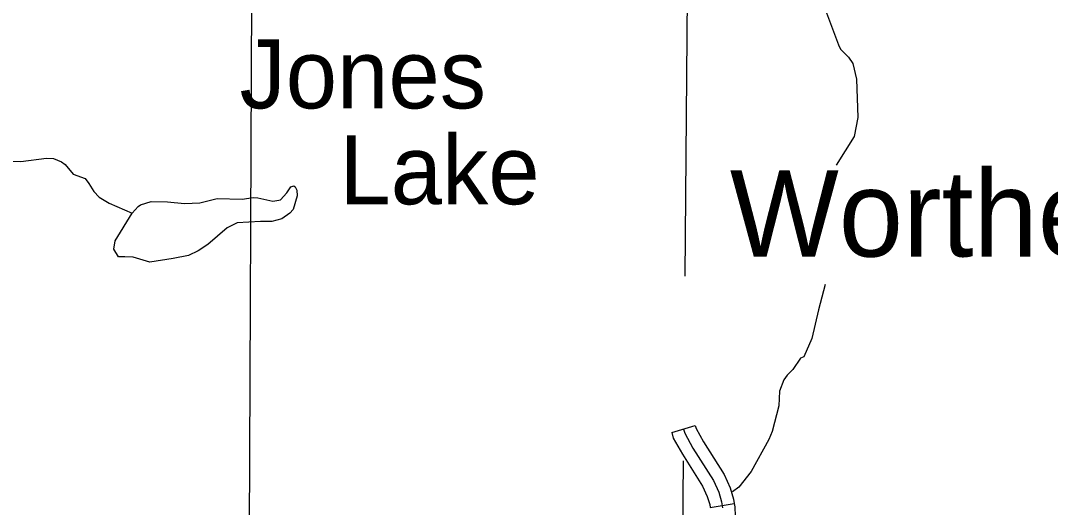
# Model space of a CAD drawing. Extents: x 1374139 to 1377472, y 1168351 to 1170484.
# Drawn here: x 1375895 to 1376021, y 1168985.7 to 1169045.3 of the extents above; entities that cross this region are included whole.
import ezdxf

# ---------------------------------------------------------------- set-up
doc = ezdxf.new("R2010")
doc.units = 0
doc.layers.add('Default', color=7, linetype='Continuous')

msp = doc.modelspace()

# ---------------------------------------------------------------- linework, layer by layer
at = {"layer": 'Default'}
for p, q in [((1375922.99, 1168982), (1375923.67, 1169140.31)), ((1375974.65, 1168994.84), (1375977.52, 1168995.7)), ((1375979.35, 1168985.68), (1375982.31, 1168986.16))]:
    msp.add_line(p, q, dxfattribs=at)
for points in [[(1375976.63, 1169058.15), (1375976.25, 1169014)], [(1375993.35, 1169046.86), (1375995.05, 1169042.32), (1375995.3, 1169041.79), (1375996.27, 1169040.79), (1375996.8, 1169040.04), (1375997.25, 1169038.1), (1375997.41, 1169033.41), (1375996.97, 1169031.09), (1375994.79, 1169027.59)], [(1375891.07, 1169028.08), (1375895.02, 1169028.02), (1375898.17, 1169028.44), (1375899.05, 1169028.38), (1375900, 1169028), (1375900.45, 1169027.67), (1375901.43, 1169026.49), (1375902.89, 1169025.96), (1375903.36, 1169025.35), (1375903.95, 1169024.34), (1375904.61, 1169023.66), (1375905.86, 1169022.91), (1375908.67, 1169021.71), (1375909.37, 1169022.51), (1375909.69, 1169022.74), (1375910.98, 1169023.13), (1375912.96, 1169023.08), (1375915.05, 1169022.87), (1375916.94, 1169022.98), (1375919.05, 1169023.51), (1375922.13, 1169023.43), (1375923.45, 1169023.64), (1375924.01, 1169023.59), (1375925.86, 1169023.18), (1375926.58, 1169023.28), (1375926.8, 1169023.34), (1375927.57, 1169024.18), (1375928.08, 1169024.92), (1375928.41, 1169025.03), (1375928.6, 1169024.93), (1375928.81, 1169024.52), (1375928.84, 1169023.83), (1375928.35, 1169022.16), (1375927.96, 1169021.69), (1375926.95, 1169021), (1375925.74, 1169020.69), (1375924.34, 1169020.69), (1375921.51, 1169020.52), (1375920.26, 1169019.91), (1375917.89, 1169017.87), (1375916.73, 1169017.09), (1375915.56, 1169016.54), (1375913.67, 1169016.14), (1375910.8, 1169015.7), (1375908.79, 1169016.32), (1375907.77, 1169016.37)], [(1375906.56, 1169018.33), (1375908.67, 1169021.71)], [(1375907.77, 1169016.37), (1375906.99, 1169016.35), (1375906.4, 1169017.3), (1375906.56, 1169018.33)], [(1375993.44, 1169012.96), (1375992.6, 1169009.85), (1375991.8, 1169006.38), (1375990.8, 1169004.13), (1375990.41, 1169003.94), (1375989.46, 1169002.57), (1375988.76, 1169001.89), (1375988.37, 1169001.3), (1375987.85, 1168999.92), (1375987.77, 1168998.11), (1375986.93, 1168994.96), (1375986.55, 1168993.99), (1375984.37, 1168990.08)], [(1375977.52, 1168995.7), (1375977.63, 1168995.36), (1375978.54, 1168993.72), (1375981.07, 1168989.71), (1375981.81, 1168988.08), (1375982.23, 1168986.7), (1375982.31, 1168986.16)], [(1375974.65, 1168994.84), (1375974.85, 1168994.18), (1375975.96, 1168992.19), (1375978.43, 1168988.28), (1375979, 1168987.02), (1375979.3, 1168986.03), (1375979.35, 1168985.68)], [(1375976.09, 1168995.27), (1375976.24, 1168994.77), (1375977.25, 1168992.95), (1375979.75, 1168988.99), (1375980.4, 1168987.55), (1375980.76, 1168986.36), (1375980.88, 1168985.62)], [(1375976.05, 1168991.37), (1375975.98, 1168982.34), (1375922.99, 1168982), (1375899.65, 1168982)], [(1375984.37, 1168990.08), (1375982.88, 1168988.16), (1375982.1, 1168987.61)], [(1375982.31, 1168986.16), (1375982.38, 1168985.76), (1375982.42, 1168984.62), (1375982.22, 1168983.68), (1375981.68, 1168982.64), (1375980.04, 1168980.46), (1375978.31, 1168978.36), (1375977.94, 1168977.79), (1375977.78, 1168977.36), (1375977.75, 1168976.75)]]:
    msp.add_lwpolyline(points, dxfattribs=at)

# ---------------------------------------------------------------- texts
for s, height, p in [('Jones', 8.448, (1375921.79, 1169034.53)), ('Lake', 8.448, (1375934, 1169022.79)), ('Worthen', 10.56, (1375981.77, 1169016.39))]:
    msp.add_text(s, height=height, dxfattribs=at).set_placement(p)

doc.saveas('drawing.dxf')
